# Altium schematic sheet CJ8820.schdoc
size 127 x 101 mm
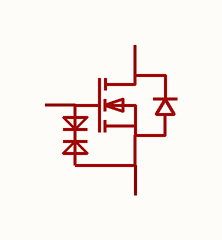
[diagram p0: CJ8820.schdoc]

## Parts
Q?  cj8820  [SOT-23-3_L2.9-W1.6-P1.90-LS2.8-BR]  (value not drawn)

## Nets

Not connected (* = marked no-connect by the designer): Q? 1(G) 2(S) 3(D)

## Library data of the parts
Q? = cj8820: 数量:1个N沟道;漏源电压(Vdss):20V;连续漏极电流(Id):7A;导通电阻(RDS(on)):21mΩ@10V;耗散功率(Pd):-;阈值电压(Vgs(th)):1.1V;; Manufacturer: CJ(江苏长电/长晶); AddInBom: yes; ModelId: 89cb27a44ab2466697082bb9fd73a7d0; ModelName: SOT-23-3L_L2.9-W1.6-H1.1-LS2.8-P0.95; ModelTransform: 114.173,110.236,0,90,0,0,0,0,0; Number: 1个N沟道; Drain to Source Voltage: 20V; Current - Continuous Drain(Id): 7A; Gate Threshold Voltage (Vgs(th)): 1.1V; Gate Charge(Qg): 8nC; Input Capacitance(Ciss): 650pF; Reverse Transfer Capacitance (Crss@Vds): 60pF; Configuration: 共漏; Type: N沟道; Output Capacitance(Coss): 140pF; Vgs: ±12V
